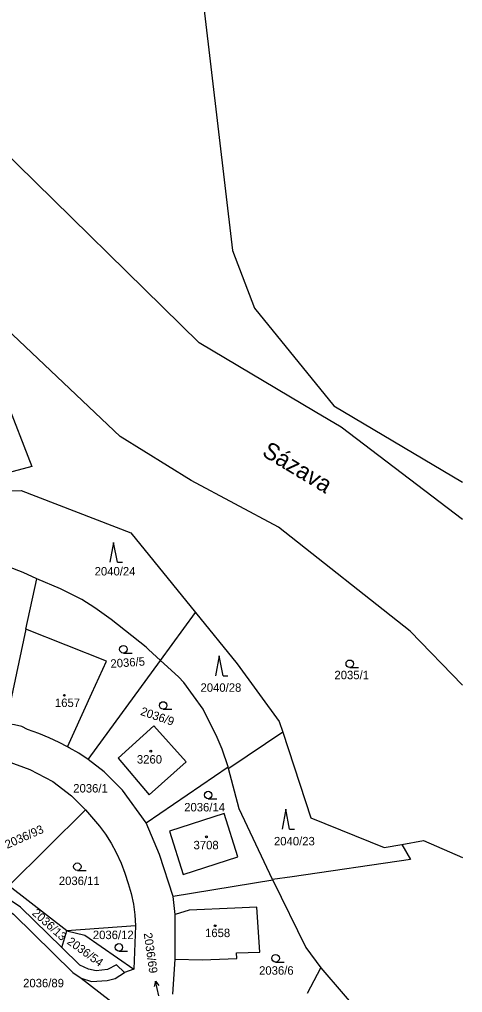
# Model space of a CAD drawing. Extents: x -667048 to -665920, y -1108425 to -1107247.
# Drawn here: x -666016.5 to -665927.3, y -1107726.9 to -1107531.2 of the extents above; entities that cross this region are included whole.
import ezdxf

# ---------------------------------------------------------------- set-up
doc = ezdxf.new("R2010")
doc.units = 0
for name, color, linetype in [('Default', 7, 'Continuous'), ('Hranice parcel', 7, 'Continuous'), ('Parcelní čísla', 7, 'Continuous'), ('Pop_ PČ_ popisy', 7, 'Continuous'), ('Značky budov', 7, 'Continuous'), ('Značky kultur', 7, 'Continuous')]:
    doc.layers.add(name, color=color, linetype=linetype)

# ---------------------------------------------------------------- blocks, each defined once
blk = doc.blocks.new('3.041')
at = {"layer": 'Default'}
blk.add_line((8, 0), (1758, 0), dxfattribs=at)
blk.add_circle((8, 750), 750, dxfattribs=at)
blk = doc.blocks.new('4.021')
at = {"layer": 'Default'}
blk.add_circle((-7, 1), 175, dxfattribs=at)
blk = doc.blocks.new('3.081')
at = {"layer": 'Default'}
for p, q in [((0, 3997), (-750, -3)), ((750, -3), (0, 3997)), ((750, -3), (1750, -3))]:
    blk.add_line(p, q, dxfattribs=at)
blk = doc.blocks.new('10291')
at = {"layer": 'Default'}
for p, q in [((0, 3001), (-500, 2001)), ((0, 1), (0, 3001)), ((0, 3001), (500, 2001))]:
    blk.add_line(p, q, dxfattribs=at)

msp = doc.modelspace()

# ---------------------------------------------------------------- linework, layer by layer
at = {"layer": 'Hranice parcel'}
for points in [[(-665927.32, -1107631.76), (-665951.75, -1107613.17), (-665956.95, -1107610.08), (-665980.3, -1107596.2), (-666020.72, -1107556.63), (-666026.53, -1107548.48), (-666031.47, -1107539.46), (-666030.14, -1107512.46), (-665994.5, -1107481.72), (-665990.06, -1107474.14)], [(-665990.06, -1107474.14), (-665980.83, -1107516.75), (-665973.63, -1107577.61), (-665969.22, -1107589.23), (-665953.21, -1107608.85), (-665927.32, -1107624.25)], [(-665927.32, -1107665.03), (-665937.88, -1107654.17), (-665964.33, -1107633.28), (-665981.95, -1107623.87), (-665996.25, -1107615.04), (-666020.36, -1107592.21)], [(-666031.24, -1107618.05), (-666033.12, -1107612.99), (-666019.3, -1107607.37), (-666014.01, -1107621.06), (-666028.36, -1107624.9), (-666029.25, -1107622.99)], [(-666038.82, -1107626.38), (-666016.14, -1107625.93), (-665994.09, -1107634.39), (-665981.04, -1107650.44)], [(-666013.02, -1107643.67), (-666015.77, -1107642.42), (-666018.71, -1107641.25), (-666021.85, -1107640.59), (-666031.19, -1107639.05), (-666040.31, -1107640.81), (-666043.09, -1107642.81)], [(-666015.18, -1107653.76), (-666013.02, -1107643.67)], [(-665988.14, -1107660.11), (-665990.52, -1107657.86), (-665991.01, -1107657.4), (-665998.07, -1107651.83), (-666001.35, -1107649.51), (-666003.97, -1107647.83), (-666004.75, -1107647.45), (-666008.25, -1107645.7), (-666013.02, -1107643.67)], [(-665988.14, -1107660.11), (-665981.04, -1107650.44)], [(-665981.04, -1107650.44), (-665972.66, -1107660.74), (-665964.2, -1107672.35), (-665963.49, -1107674.51)], [(-666015.18, -1107653.76), (-666019.23, -1107672.73)], [(-666006.82, -1107677.45), (-666005.5, -1107674.52), (-666001.93, -1107666.65), (-665999.01, -1107660.23), (-666015.18, -1107653.76)], [(-666002.68, -1107680.02), (-665988.14, -1107660.11)], [(-665974.5, -1107681.46), (-665975.69, -1107677.93), (-665976.7, -1107675.55), (-665979.5, -1107669.85), (-665983.4, -1107664.51), (-665984.49, -1107663.36), (-665988.14, -1107660.11)], [(-666006.82, -1107677.45), (-666008.51, -1107676.59), (-666010.53, -1107675.64), (-666012.61, -1107674.8), (-666014.86, -1107673.96), (-666016.01, -1107673.37), (-666017.49, -1107673.04), (-666019.23, -1107672.73)], [(-665982.95, -1107680.44), (-665989.43, -1107673.26), (-665996.64, -1107679.71)], [(-665963.49, -1107674.51), (-665974.13, -1107681.66), (-665974.4, -1107681.84)], [(-665963.49, -1107674.51), (-665957.88, -1107691.71), (-665943.06, -1107697.71), (-665939.54, -1107697.07)], [(-666002.68, -1107680.02), (-666004.56, -1107678.75), (-666006.5, -1107677.62), (-666006.82, -1107677.45)], [(-666029.24, -1107679.91), (-666024.27, -1107679.81), (-666018.96, -1107680.36), (-666014.38, -1107682.04), (-666009.79, -1107684.43), (-666006.01, -1107687.29), (-666003.21, -1107690.1)], [(-665991.02, -1107692.76), (-665995.76, -1107686.18), (-665997.62, -1107684.27), (-665999.42, -1107682.51), (-666002.68, -1107680.02)], [(-665996.64, -1107679.71), (-665990.36, -1107687.12), (-665982.95, -1107680.44)], [(-665991.02, -1107692.76), (-665974.5, -1107681.46)], [(-665974.4, -1107681.84), (-665974.5, -1107681.46)], [(-665965.56, -1107704.14), (-665972.3, -1107689.94), (-665974.4, -1107681.84)], [(-666016.3, -1107709.69), (-666033.36, -1107698.28), (-666051.05, -1107689.67)], [(-666052.47, -1107691.28), (-666034.33, -1107699.82), (-666017.67, -1107711.11), (-666005.73, -1107722.82), (-666004.06, -1107724)], [(-666018.63, -1107705.41), (-666003.21, -1107690.1)], [(-666003.21, -1107690.1), (-666000.4, -1107693.4), (-665999.2, -1107695), (-665998.06, -1107696.83), (-665997, -1107698.72), (-665996.03, -1107700.83), (-665995.27, -1107702.85), (-665994.62, -1107704.91), (-665994.02, -1107706.98), (-665993.54, -1107709.09), (-665993.26, -1107711.23), (-665993.14, -1107713.43)], [(-665975.31, -1107690.89), (-665986.31, -1107694.43), (-665983.52, -1107703.11), (-665972.52, -1107699.57), (-665975.31, -1107690.89)], [(-665985.59, -1107707.57), (-665988.29, -1107699.13), (-665991.02, -1107692.76)], [(-665939.54, -1107697.07), (-665937.79, -1107700.14), (-665961.62, -1107703.57), (-665965.56, -1107704.14)], [(-665939.54, -1107697.07), (-665935.21, -1107696.29), (-665927.32, -1107699.71)], [(-666006.95, -1107714.45), (-666018.63, -1107705.41)], [(-665965.5, -1107704.26), (-665985.59, -1107707.57)], [(-665965.56, -1107704.14), (-665965.5, -1107704.26)], [(-665965.5, -1107704.26), (-665958.83, -1107717.81), (-665955.87, -1107721.88)], [(-665985.19, -1107711.15), (-665985.59, -1107707.57)], [(-666007.98, -1107717.82), (-666016.3, -1107709.69)], [(-665985.17, -1107720.14), (-665979.74, -1107720.28), (-665972.77, -1107720), (-665972.81, -1107718.9), (-665968.11, -1107718.78), (-665968.69, -1107709.71), (-665973.15, -1107709.9), (-665982.37, -1107710.29), (-665985.19, -1107711.15)], [(-665985.17, -1107720.14), (-665985.19, -1107711.15)], [(-666007.98, -1107717.82), (-666006.95, -1107714.45)], [(-665993.14, -1107713.43), (-666006.95, -1107714.45)], [(-666006.95, -1107714.45), (-666003.36, -1107715.3), (-665993.45, -1107722.19)], [(-665993.14, -1107713.43), (-665993.45, -1107722.19)], [(-666004.37, -1107721.34), (-666007.98, -1107717.82)], [(-665985.61, -1107727.21), (-665985.17, -1107720.14)], [(-665995.37, -1107722.85), (-665996.96, -1107721.32), (-665998.78, -1107722.24), (-666001.05, -1107722.5), (-666002.62, -1107722.14), (-666004.37, -1107721.34)], [(-666004.06, -1107724), (-666002.01, -1107724.65), (-665998.84, -1107724.42), (-665997.25, -1107724.07), (-665995.37, -1107722.85)], [(-665993.45, -1107722.19), (-665995.37, -1107722.85)], [(-665958.54, -1107727.02), (-665955.87, -1107721.88)], [(-665955.87, -1107721.88), (-665946.87, -1107732.34)], [(-666004.06, -1107724), (-665986.55, -1107737.54)]]:
    msp.add_lwpolyline(points, dxfattribs=at)

# ---------------------------------------------------------------- block references
at = {"layer": 'Pop_ PČ_ popisy', "xscale": 0.0010000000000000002, "yscale": 0.0010000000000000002, "rotation": 13.000000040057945}
msp.add_blockref('10291', (-665988.45, -1107727.51), dxfattribs=at)
at = {"layer": 'Značky budov', "xscale": 0.0010000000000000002, "yscale": 0.0010000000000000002}
for p in [(-666007.45, -1107667.09), (-665990.06, -1107678.33), (-665978.86, -1107695.55), (-665977.1, -1107713.43)]:
    msp.add_blockref('4.021', p, dxfattribs=at)
at = {"layer": 'Značky kultur', "xscale": 0.0010000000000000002, "yscale": 0.0010000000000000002}
for name, p in [('3.081', (-665997.54, -1107640.32)), ('3.041', (-665995.59, -1107658.58)), ('3.081', (-665976.28, -1107663.17)), ('3.041', (-665950.03, -1107661.49)), ('3.041', (-665987.59, -1107669.87)), ('3.041', (-665978.53, -1107687.89)), ('3.081', (-665962.88, -1107693.98)), ('3.041', (-666004.85, -1107702.3)), ('3.041', (-665996.49, -1107718.53)), ('3.041', (-665964.95, -1107720.73))]:
    msp.add_blockref(name, p, dxfattribs=at)

# ---------------------------------------------------------------- texts
at = {"layer": 'Parcelní čísla'}
for s, p in [('2040/24', (-666001.36, -1107642.99)), ('2035/1', (-665953.1, -1107663.85)), ('2040/28', (-665980.06, -1107666.38)), ('1657', (-666009.36, -1107669.44)), ('3260', (-665992.86, -1107680.82)), ('2036/1', (-666005.67, -1107686.64)), ('2036/14', (-665983.34, -1107690.44)), ('2040/23', (-665965.27, -1107697.27)), ('3708', (-665981.46, -1107698.06)), ('2036/11', (-666008.57, -1107705.25)), ('2036/12', (-666001.73, -1107716.12)), ('1658', (-665979.14, -1107715.72)), ('2036/6', (-665968.27, -1107723.28)), ('2036/89', (-666015.76, -1107725.81))]:
    msp.add_text(s, height=1.7, dxfattribs=at).set_placement(p)
for s, rotation, p in [('2036/5', 4, (-665998.12, -1107661.58)), ('2036/9', 341, (-665992.28, -1107670.99)), ('2036/93', 24, (-666018.96, -1107697.98)), ('2036/13', 318, (-666014.08, -1107711.08)), ('2036/69', 278, (-665991.49, -1107714.96)), ('2036/54', 324, (-666007.06, -1107716.94))]:
    msp.add_text(s, height=1.7, rotation=rotation, dxfattribs=at).set_placement(p)
at = {"layer": 'Pop_ PČ_ popisy'}
msp.add_text('Sázava', height=3.4, rotation=329, dxfattribs=at).set_placement((-665967.89, -1107618.77))

doc.saveas('drawing.dxf')
